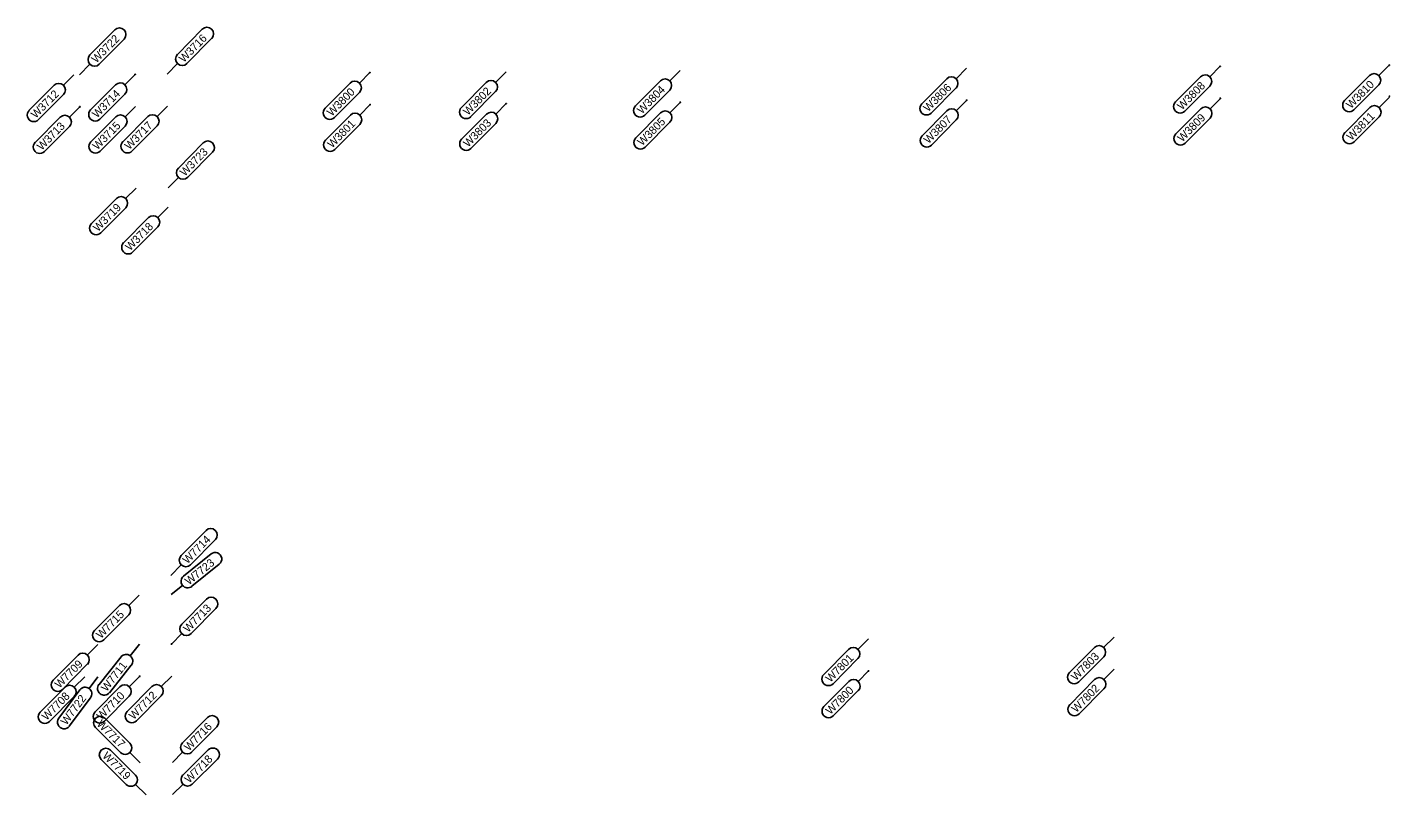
# Model space of a CAD drawing. Extents: x 12479652 to 12487250, y 9842710 to 9846560.
# Drawn here: x 12486497.4 to 12486710.2, y 9842760.5 to 9842880.4 of the extents above; entities that cross this region are included whole.
import ezdxf

# ---------------------------------------------------------------- set-up
doc = ezdxf.new("R2010")
doc.units = 0
doc.layers.add('_CIVIL_CONSTRUCTION', color=7, linetype='Continuous')
doc.layers.add('TextAlignmentLrg', color=7, linetype='Continuous')

msp = doc.modelspace()

# ---------------------------------------------------------------- linework, layer by layer
at = {"layer": '_CIVIL_CONSTRUCTION'}
for p, q in [((12486511.1, 9842879.97), (12486507.23, 9842876.04)), ((12486508.69, 9842874.6), (12486512.56, 9842878.52)), ((12486524.78, 9842880.07), (12486520.91, 9842876.14)), ((12486522.37, 9842874.7), (12486526.24, 9842878.63)), ((12486505.62, 9842872.95), (12486507.24, 9842874.59)), ((12486519.3, 9842873.05), (12486520.92, 9842874.69)), ((12486683.75, 9842874.27), (12486682.12, 9842872.64)), ((12486710.15, 9842874.46), (12486708.52, 9842872.83)), ((12486504.7, 9842872.94), (12486503.08, 9842871.31)), ((12486514.3, 9842873.01), (12486512.68, 9842871.38)), ((12486550.94, 9842873.29), (12486549.32, 9842871.65)), ((12486572.21, 9842873.4), (12486570.59, 9842871.77)), ((12486599.4, 9842873.64), (12486597.78, 9842872.01)), ((12486637.16, 9842868.43), (12486641.05, 9842872.34)), ((12486644.12, 9842873.97), (12486642.5, 9842872.34)), ((12486676.78, 9842868.72), (12486680.67, 9842872.63)), ((12486703.18, 9842868.91), (12486707.07, 9842872.83)), ((12486497.74, 9842867.4), (12486501.63, 9842871.31)), ((12486507.34, 9842867.47), (12486511.23, 9842871.38)), ((12486512.69, 9842869.93), (12486508.8, 9842866.02)), ((12486543.98, 9842867.74), (12486547.87, 9842871.65)), ((12486549.33, 9842870.2), (12486545.44, 9842866.29)), ((12486565.24, 9842867.86), (12486569.13, 9842871.77)), ((12486570.59, 9842870.32), (12486566.7, 9842866.41)), ((12486592.43, 9842868.09), (12486596.32, 9842872.01)), ((12486597.78, 9842870.56), (12486593.89, 9842866.65)), ((12486642.5, 9842870.89), (12486638.61, 9842866.98)), ((12486682.13, 9842871.18), (12486678.24, 9842867.27)), ((12486708.53, 9842871.38), (12486704.64, 9842867.47)), ((12486503.08, 9842869.86), (12486499.19, 9842865.95)), ((12486505.66, 9842867.95), (12486504.04, 9842866.32)), ((12486514.34, 9842868.01), (12486512.72, 9842866.38)), ((12486519.34, 9842868.05), (12486517.72, 9842866.42)), ((12486550.98, 9842868.29), (12486549.36, 9842866.65)), ((12486572.24, 9842868.44), (12486570.62, 9842866.81)), ((12486599.43, 9842868.64), (12486597.81, 9842867.01)), ((12486644.16, 9842868.97), (12486642.53, 9842867.34)), ((12486683.78, 9842869.27), (12486682.16, 9842867.64)), ((12486703.22, 9842863.91), (12486707.11, 9842867.83)), ((12486710.18, 9842869.46), (12486708.56, 9842867.83)), ((12486498.7, 9842862.4), (12486502.58, 9842866.31)), ((12486507.38, 9842862.47), (12486511.27, 9842866.38)), ((12486512.38, 9842862.5), (12486516.27, 9842866.42)), ((12486544.02, 9842862.74), (12486547.91, 9842866.65)), ((12486565.28, 9842862.89), (12486569.17, 9842866.81)), ((12486592.47, 9842863.1), (12486596.36, 9842867.01)), ((12486637.19, 9842863.43), (12486641.08, 9842867.34)), ((12486642.54, 9842865.89), (12486638.65, 9842861.98)), ((12486676.82, 9842863.72), (12486680.71, 9842867.63)), ((12486682.16, 9842866.18), (12486678.28, 9842862.27)), ((12486708.56, 9842866.38), (12486704.68, 9842862.47)), ((12486504.04, 9842864.87), (12486500.15, 9842860.96)), ((12486512.72, 9842864.93), (12486508.83, 9842861.02)), ((12486517.72, 9842864.97), (12486513.83, 9842861.06)), ((12486549.36, 9842865.2), (12486545.47, 9842861.29)), ((12486570.63, 9842865.36), (12486566.74, 9842861.45)), ((12486597.82, 9842865.56), (12486593.93, 9842861.65)), ((12486524.92, 9842862.31), (12486521.04, 9842858.38)), ((12486522.5, 9842856.94), (12486526.38, 9842860.87)), ((12486514.43, 9842855.26), (12486512.81, 9842853.63)), ((12486519.43, 9842855.29), (12486521.05, 9842856.93)), ((12486507.47, 9842849.71), (12486511.36, 9842853.62)), ((12486512.82, 9842852.17), (12486508.93, 9842848.26)), ((12486519.46, 9842852.28), (12486517.83, 9842850.65)), ((12486512.49, 9842846.73), (12486516.38, 9842850.64)), ((12486517.84, 9842849.2), (12486513.95, 9842845.29)), ((12486525.36, 9842801.8), (12486521.49, 9842797.87)), ((12486522.95, 9842796.43), (12486526.82, 9842800.36)), ((12486526.14, 9842798.13), (12486521.85, 9842794.66)), ((12486519.88, 9842794.78), (12486521.5, 9842796.42)), ((12486523.14, 9842793.07), (12486527.43, 9842796.53)), ((12486514.9, 9842791.7), (12486513.28, 9842790.07)), ((12486519.9, 9842791.78), (12486521.69, 9842793.22)), ((12486507.94, 9842786.15), (12486511.83, 9842790.07)), ((12486525.44, 9842791.07), (12486521.57, 9842787.14)), ((12486523.03, 9842785.7), (12486526.9, 9842789.63)), ((12486513.29, 9842788.62), (12486509.4, 9842784.71)), ((12486519.96, 9842784.05), (12486521.58, 9842785.69)), ((12486628.8, 9842784.86), (12486627.17, 9842783.23)), ((12486667.17, 9842785.14), (12486665.55, 9842783.51)), ((12486508.44, 9842783.97), (12486506.82, 9842782.34)), ((12486514.96, 9842784.02), (12486513.53, 9842782.22)), ((12486621.83, 9842779.31), (12486625.72, 9842783.22)), ((12486660.21, 9842779.59), (12486664.1, 9842783.51)), ((12486501.48, 9842778.42), (12486505.37, 9842782.33)), ((12486506.82, 9842780.89), (12486502.93, 9842776.97)), ((12486508.65, 9842777.74), (12486512.09, 9842782.05)), ((12486513.69, 9842780.78), (12486510.26, 9842776.46)), ((12486627.18, 9842781.78), (12486623.29, 9842777.86)), ((12486665.56, 9842782.06), (12486661.67, 9842778.15)), ((12486506.41, 9842778.95), (12486504.79, 9842777.32)), ((12486508.47, 9842778.96), (12486507.1, 9842777.11)), ((12486515, 9842779.02), (12486513.38, 9842777.39)), ((12486520, 9842779.05), (12486518.38, 9842777.42)), ((12486628.83, 9842779.86), (12486627.21, 9842778.23)), ((12486660.25, 9842774.59), (12486664.14, 9842778.51)), ((12486667.21, 9842780.14), (12486665.59, 9842778.51)), ((12486499.45, 9842773.41), (12486503.34, 9842777.32)), ((12486502.37, 9842772.48), (12486505.66, 9842776.9)), ((12486508.04, 9842773.47), (12486511.92, 9842777.38)), ((12486513.04, 9842773.51), (12486516.92, 9842777.42)), ((12486621.87, 9842774.31), (12486625.76, 9842778.22)), ((12486627.22, 9842776.78), (12486623.33, 9842772.86)), ((12486665.59, 9842777.06), (12486661.7, 9842773.15)), ((12486504.79, 9842775.87), (12486500.9, 9842771.96)), ((12486507.31, 9842775.68), (12486504.01, 9842771.25)), ((12486513.38, 9842775.94), (12486509.49, 9842772.02)), ((12486518.38, 9842775.97), (12486514.49, 9842772.06)), ((12486509.55, 9842772.48), (12486513.46, 9842768.59)), ((12486525.58, 9842772.57), (12486521.7, 9842768.64)), ((12486512.01, 9842767.13), (12486508.1, 9842771.02)), ((12486523.16, 9842767.2), (12486527.04, 9842771.13)), ((12486512.91, 9842762.14), (12486509, 9842766.03)), ((12486510.44, 9842767.49), (12486514.36, 9842763.6)), ((12486515.1, 9842765.52), (12486513.47, 9842767.14)), ((12486520.1, 9842765.55), (12486521.71, 9842767.19)), ((12486525.68, 9842767.52), (12486521.77, 9842763.63)), ((12486523.22, 9842762.17), (12486527.13, 9842766.06)), ((12486515.99, 9842760.52), (12486514.36, 9842762.15)), ((12486520.13, 9842760.55), (12486521.77, 9842762.18))]:
    msp.add_line(p, q, dxfattribs=at)
for centre, start, end in [((12486511.83, 9842879.24), 315.3788, 135.3788), ((12486525.51, 9842879.35), 315.3788, 135.3788), ((12486507.96, 9842875.32), 135.3788, 315.3788), ((12486521.64, 9842875.42), 135.3788, 315.3788), ((12486569.86, 9842871.04), 315.1702, 135.1702), ((12486597.05, 9842871.28), 315.1702, 135.1702), ((12486641.77, 9842871.61), 315.1702, 135.1702), ((12486681.4, 9842871.91), 315.1702, 135.1702), ((12486707.8, 9842872.1), 315.1702, 135.1702), ((12486502.36, 9842870.58), 315.1702, 135.1702), ((12486511.96, 9842870.66), 315.1702, 135.1702), ((12486548.6, 9842870.93), 315.1702, 135.1702), ((12486565.97, 9842867.13), 135.1702, 315.1702), ((12486593.16, 9842867.37), 135.1702, 315.1702), ((12486637.88, 9842867.7), 135.1702, 315.1702), ((12486677.51, 9842867.99), 135.1702, 315.1702), ((12486681.44, 9842866.91), 315.1702, 135.1702), ((12486703.91, 9842868.19), 135.1702, 315.1702), ((12486707.84, 9842867.1), 315.1702, 135.1702), ((12486498.47, 9842866.67), 135.1702, 315.1702), ((12486503.31, 9842865.59), 315.1702, 135.1702), ((12486508.07, 9842866.74), 135.1702, 315.1702), ((12486511.99, 9842865.66), 315.1702, 135.1702), ((12486516.99, 9842865.69), 315.1702, 135.1702), ((12486544.71, 9842867.01), 135.1702, 315.1702), ((12486548.64, 9842865.93), 315.1702, 135.1702), ((12486569.9, 9842866.08), 315.1702, 135.1702), ((12486597.09, 9842866.28), 315.1702, 135.1702), ((12486641.81, 9842866.62), 315.1702, 135.1702), ((12486677.55, 9842863), 135.1702, 315.1702), ((12486703.95, 9842863.19), 135.1702, 315.1702), ((12486499.42, 9842861.68), 135.1702, 315.1702), ((12486508.11, 9842861.74), 135.1702, 315.1702), ((12486513.1, 9842861.78), 135.1702, 315.1702), ((12486525.65, 9842861.59), 315.3788, 135.3788), ((12486544.75, 9842862.01), 135.1702, 315.1702), ((12486566.01, 9842862.17), 135.1702, 315.1702), ((12486593.2, 9842862.37), 135.1702, 315.1702), ((12486637.92, 9842862.7), 135.1702, 315.1702), ((12486521.77, 9842857.66), 135.3788, 315.3788), ((12486512.09, 9842852.9), 315.1702, 135.1702), ((12486517.11, 9842849.92), 315.1702, 135.1702), ((12486508.2, 9842848.99), 135.1702, 315.1702), ((12486513.22, 9842846.01), 135.1702, 315.1702), ((12486526.09, 9842801.08), 315.3788, 135.3788), ((12486522.22, 9842797.15), 135.3788, 315.3788), ((12486526.79, 9842797.33), 308.8973, 128.8973), ((12486522.49, 9842793.87), 128.8973, 308.8973), ((12486526.17, 9842790.35), 315.3788, 135.3788), ((12486512.56, 9842789.34), 315.1702, 135.1702), ((12486522.3, 9842786.42), 135.3788, 315.3788), ((12486508.67, 9842785.43), 135.1702, 315.1702), ((12486626.45, 9842782.5), 315.1702, 135.1702), ((12486664.83, 9842782.78), 315.1702, 135.1702), ((12486506.1, 9842781.61), 315.1702, 135.1702), ((12486512.89, 9842781.41), 321.4946, 141.4946), ((12486502.21, 9842777.7), 135.1702, 315.1702), ((12486622.56, 9842778.59), 135.1702, 315.1702), ((12486626.49, 9842777.5), 315.1702, 135.1702), ((12486660.94, 9842778.87), 135.1702, 315.1702), ((12486664.86, 9842777.78), 315.1702, 135.1702), ((12486504.06, 9842776.59), 315.1702, 135.1702), ((12486506.49, 9842776.29), 323.325, 143.325), ((12486509.45, 9842777.1), 141.4946, 321.4946), ((12486512.65, 9842776.66), 315.1702, 135.1702), ((12486517.65, 9842776.7), 315.1702, 135.1702), ((12486622.6, 9842773.59), 135.1702, 315.1702), ((12486660.98, 9842773.87), 135.1702, 315.1702), ((12486500.18, 9842772.68), 135.1702, 315.1702), ((12486503.19, 9842771.86), 143.325, 323.325), ((12486508.76, 9842772.75), 135.1702, 315.1702), ((12486508.83, 9842771.75), 45.1702, 225.1702), ((12486513.76, 9842772.78), 135.1702, 315.1702), ((12486526.31, 9842771.85), 315.3788, 135.3788), ((12486509.72, 9842766.76), 45.1702, 225.1702), ((12486512.74, 9842767.86), 225.1702, 45.1702), ((12486522.43, 9842767.92), 135.3788, 315.3788), ((12486526.41, 9842766.79), 314.8298, 134.8298), ((12486513.63, 9842762.87), 225.1702, 45.1702), ((12486522.49, 9842762.9), 134.8298, 314.8298)]:
    msp.add_arc(centre, 1.03, start, end, dxfattribs=at)
at = {"layer": 'TextAlignmentLrg'}
for centre in [(12486683.75, 9842874.27), (12486710.15, 9842874.46), (12486514.3, 9842873.01), (12486550.94, 9842873.29), (12486505.66, 9842867.95), (12486550.98, 9842868.29), (12486572.24, 9842868.44), (12486599.43, 9842868.64), (12486644.16, 9842868.97), (12486683.78, 9842869.27), (12486710.18, 9842869.6), (12486519.96, 9842784.05), (12486515, 9842779.02), (12486628.83, 9842779.86)]:
    msp.add_circle(centre, 0.05, dxfattribs=at)

# ---------------------------------------------------------------- texts
at = {"layer": '_CIVIL_CONSTRUCTION'}
for s, rotation, p in [('W3722', 45.3788, (12486508.23, 9842874.69)), ('W3716', 45.3788, (12486521.89, 9842874.77)), ('W3712', 45.1702, (12486498.76, 9842866.06)), ('W3714', 45.1702, (12486508.33, 9842866.11)), ('W3800', 45.1702, (12486544.98, 9842866.39)), ('W3802', 45.1702, (12486566.26, 9842866.52)), ('W3804', 45.1702, (12486593.43, 9842866.74)), ('W3806', 45.1702, (12486638.15, 9842867.07)), ('W3808', 45.1702, (12486677.78, 9842867.37)), ('W3810', 45.1702, (12486704.18, 9842867.56)), ('W3715', 45.1702, (12486508.39, 9842861.13)), ('W3717', 45.1702, (12486513.39, 9842861.16)), ('W3801', 45.1702, (12486545.05, 9842861.42)), ('W3803', 45.1702, (12486566.29, 9842861.55)), ('W3805', 45.1702, (12486593.48, 9842861.76)), ('W3807', 45.1702, (12486638.2, 9842862.09)), ('W3809', 45.1702, (12486677.82, 9842862.37)), ('W3811', 45.1702, (12486704.25, 9842862.6)), ('W3713', 45.1702, (12486499.7, 9842861.06)), ('W3723', 45.3788, (12486522.03, 9842857.02)), ('W3719', 45.1702, (12486508.47, 9842848.36)), ('W3718', 45.1702, (12486513.49, 9842845.38)), ('W7714', 45.3788, (12486522.46, 9842796.49)), ('W7723', 38.8973, (12486522.68, 9842793.2)), ('W7715', 45.1702, (12486508.95, 9842784.81)), ('W7713', 45.3788, (12486522.56, 9842785.78)), ('W7803', 45.1702, (12486661.22, 9842778.25)), ('W7709', 45.1702, (12486502.48, 9842777.07)), ('W7711', 51.4946, (12486509.83, 9842776.54)), ('W7801', 45.1702, (12486622.87, 9842777.99)), ('W7708', 45.1702, (12486500.45, 9842772.05)), ('W7710', 45.1702, (12486509.03, 9842772.12)), ('W7712', 45.1702, (12486514.05, 9842772.17)), ('W7800', 45.1702, (12486622.87, 9842772.96)), ('W7802', 45.1702, (12486661.27, 9842773.26)), ('W7722', 53.325, (12486503.56, 9842771.3)), ('W7717', 315.1702, (12486508.21, 9842771.47)), ('W7716', 45.3788, (12486522.68, 9842767.27)), ('W7719', 315.1702, (12486509.09, 9842766.49)), ('W7718', 44.8298, (12486522.74, 9842762.25))]:
    msp.add_text(s, height=1.25, rotation=rotation, dxfattribs=at).set_placement(p)

doc.saveas('drawing.dxf')
